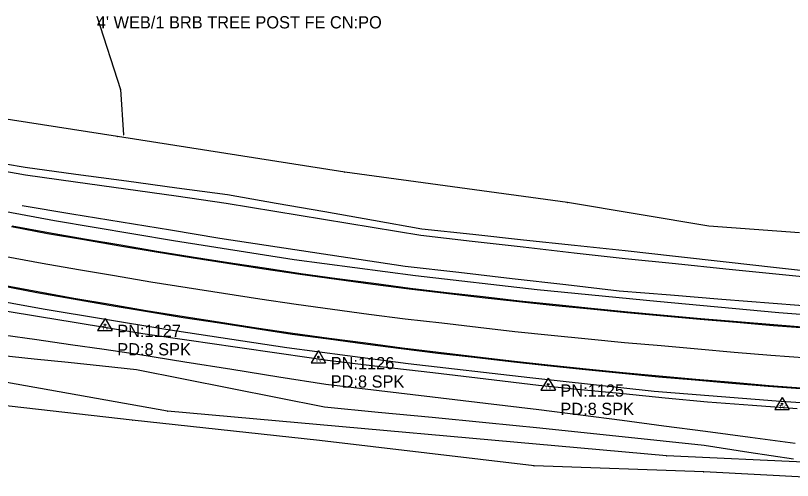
# Model space of a CAD drawing. Extents: x 878399 to 889864, y 1564003 to 1567413.
# Drawn here: x 886472.5 to 886790, y 1564428.6 to 1564618.5 of the extents above; entities that cross this region are included whole.
import ezdxf

# ---------------------------------------------------------------- set-up
doc = ezdxf.new("R2010")
doc.units = 0
for name, color, linetype in [('S_DITCHLINE', 7, 'Continuous'), ('S_EDGE_PAVEMENT', 7, 'Continuous'), ('S_FENCE', 7, 'Continuous'), ('S_FENCE_ANNOT', 7, 'Continuous'), ('S_FIBER_OPTIC_CABLE', 7, 'Continuous'), ('S_MSC_PT_SYM', 7, 'Continuous'), ('S_PAVEMENT_CROWN', 7, 'Continuous'), ('S_SECONDARY_CTL', 7, 'Continuous'), ('S_SECONDARY_CTL_ANNOT', 7, 'Continuous'), ('S_SHOULDER', 7, 'Continuous'), ('S_UTL_PT_SYM', 7, 'Continuous')]:
    doc.layers.add(name, color=color, linetype=linetype)

msp = doc.modelspace()

# ---------------------------------------------------------------- linework, layer by layer
at = {"layer": 'S_DITCHLINE'}
for points in [[(886921.18, 1564509.16), (886900.59, 1564510.35), (886880, 1564511.54), (886859.42, 1564512.73), (886838.83, 1564513.91), (886821.46, 1564513.53), (886804.1, 1564513.14), (886783.47, 1564515.43), (886762.84, 1564517.72), (886742.22, 1564520.01), (886721.59, 1564522.3), (886700.83, 1564524.54), (886680.07, 1564526.78), (886659.31, 1564529.03), (886638.55, 1564531.27), (886618.68, 1564534.76), (886598.81, 1564538.24), (886578.94, 1564541.73), (886559.07, 1564545.22), (886538.41, 1564548), (886517.75, 1564550.79), (886497.08, 1564553.58), (886476.42, 1564556.37), (886460.17, 1564559.13)], [(886803.75, 1564510.75), (886783.22, 1564512.83), (886762.69, 1564514.91), (886742.15, 1564516.99), (886721.62, 1564519.07), (886700.75, 1564521.45), (886679.88, 1564523.82), (886659.01, 1564526.2), (886638.14, 1564528.58), (886618.25, 1564531.87), (886598.36, 1564535.16), (886578.47, 1564538.45), (886558.58, 1564541.75), (886538.06, 1564544.63), (886517.54, 1564547.5), (886497.01, 1564550.38), (886476.49, 1564553.26), (886460.26, 1564556.16)], [(886791.03, 1564443.59), (886772.71, 1564446.08), (886754.4, 1564448.57), (886737.37, 1564450.78), (886720.35, 1564453), (886703.32, 1564455.21), (886686.3, 1564457.42), (886664.55, 1564460), (886642.79, 1564462.57), (886621.04, 1564465.15), (886599.29, 1564467.72), (886580.08, 1564470.79), (886560.87, 1564473.86), (886541.67, 1564476.93), (886522.46, 1564480.01), (886508.69, 1564482), (886494.93, 1564483.99), (886481.16, 1564485.98), (886467.4, 1564487.97)], [(886790.33, 1564437.19), (886772.14, 1564439.98), (886753.94, 1564442.77), (886737.12, 1564444.57), (886720.3, 1564446.37), (886703.47, 1564448.17), (886686.65, 1564449.97), (886664.66, 1564452.1), (886642.67, 1564454.24), (886620.68, 1564456.38), (886598.69, 1564458.52), (886579.49, 1564462.35), (886560.28, 1564466.17), (886541.08, 1564469.99), (886521.88, 1564473.81), (886507.94, 1564475.25), (886493.99, 1564476.69), (886480.05, 1564478.13), (886466.11, 1564479.57)]]:
    msp.add_lwpolyline(points, dxfattribs=at)
at = {"layer": 'S_EDGE_PAVEMENT'}
for points in [[(886470.81, 1564532.26), (886485.56, 1564529.5), (886485.56, 1564529.5), (886500.34, 1564526.95), (886515.13, 1564524.44), (886529.92, 1564521.93), (886544.28, 1564519.61), (886559.1, 1564517.32), (886573.93, 1564515.02), (886588.77, 1564512.79), (886603.63, 1564510.79), (886618.5, 1564508.79), (886633.37, 1564506.8), (886648.27, 1564505.06), (886663.18, 1564503.35), (886678.08, 1564501.65), (886693.01, 1564500.07), (886707.39, 1564498.64), (886722.32, 1564497.17), (886737.26, 1564495.74), (886752.2, 1564494.45), (886752.2, 1564494.45), (886767.15, 1564493.17), (886782.1, 1564491.89), (886797.05, 1564490.73)], [(886471.14, 1564532.59), (886485.89, 1564529.83), (886485.89, 1564529.83), (886500.67, 1564527.29), (886515.46, 1564524.77), (886530.25, 1564522.26), (886544.6, 1564519.94), (886559.43, 1564517.65), (886574.25, 1564515.35), (886589.09, 1564513.12), (886603.96, 1564511.12), (886618.82, 1564509.13), (886633.69, 1564507.13), (886648.59, 1564505.39), (886663.5, 1564503.68), (886678.4, 1564501.98), (886693.33, 1564500.4), (886707.71, 1564498.98), (886722.64, 1564497.5), (886737.57, 1564496.07), (886752.52, 1564494.78), (886752.52, 1564494.78), (886767.46, 1564493.5), (886782.41, 1564492.22), (886797.37, 1564491.06)], [(886466.46, 1564508.17), (886481.19, 1564505.34), (886481.19, 1564505.34), (886481.19, 1564505.34), (886495.97, 1564502.74), (886495.97, 1564502.74), (886510.75, 1564500.21), (886525.54, 1564497.69), (886525.54, 1564497.69), (886541, 1564495.16), (886541, 1564495.16), (886555.83, 1564492.89), (886570.66, 1564490.62), (886570.66, 1564490.62), (886585.49, 1564488.37), (886585.49, 1564488.37), (886600.36, 1564486.39), (886600.36, 1564486.39), (886600.36, 1564486.39), (886615.23, 1564484.41), (886615.23, 1564484.41), (886630.1, 1564482.43), (886630.1, 1564482.43), (886645, 1564480.61), (886645, 1564480.61), (886645, 1564480.61), (886659.9, 1564478.86), (886659.9, 1564478.86), (886659.9, 1564478.86), (886674.8, 1564477.1), (886674.8, 1564477.1), (886674.8, 1564477.1), (886689.71, 1564475.46), (886705.38, 1564473.88), (886720.31, 1564472.38), (886720.31, 1564472.38), (886735.24, 1564470.9), (886735.24, 1564470.9), (886735.24, 1564470.9), (886750.19, 1564469.62), (886750.19, 1564469.62), (886765.13, 1564468.34), (886765.13, 1564468.34), (886765.13, 1564468.34), (886780.08, 1564467.06), (886795.04, 1564465.92)], [(886466.79, 1564508.51), (886481.52, 1564505.68), (886481.52, 1564505.68), (886481.52, 1564505.68), (886496.29, 1564503.07), (886496.29, 1564503.07), (886511.08, 1564500.55), (886525.87, 1564498.02), (886525.87, 1564498.02), (886541.32, 1564495.49), (886541.32, 1564495.49), (886556.15, 1564493.22), (886570.98, 1564490.95), (886570.98, 1564490.95), (886585.82, 1564488.71), (886585.82, 1564488.71), (886600.69, 1564486.72), (886600.69, 1564486.72), (886600.69, 1564486.72), (886615.56, 1564484.74), (886615.56, 1564484.74), (886630.42, 1564482.76), (886630.42, 1564482.76), (886645.32, 1564480.95), (886645.32, 1564480.95), (886645.32, 1564480.95), (886660.21, 1564479.19), (886660.21, 1564479.19), (886660.21, 1564479.19), (886675.11, 1564477.44), (886675.11, 1564477.44), (886675.11, 1564477.44), (886690.03, 1564475.79), (886705.7, 1564474.21), (886720.63, 1564472.71), (886720.63, 1564472.71), (886735.55, 1564471.23), (886735.55, 1564471.23), (886735.55, 1564471.23), (886750.5, 1564469.95), (886750.5, 1564469.95), (886765.45, 1564468.67), (886765.45, 1564468.67), (886765.45, 1564468.67), (886780.39, 1564467.39), (886795.35, 1564466.26)]]:
    msp.add_lwpolyline(points, dxfattribs=at)
at = {"layer": 'S_FENCE'}
for p, q in [((886505.67, 1564618.21), (886515.41, 1564588.28)), ((886515.41, 1564588.28), (886516.64, 1564569.76)), ((886514.17, 1564569.01), (886437.4, 1564581)), ((886607, 1564554.55), (886514.17, 1564569.01)), ((886698.08, 1564542.05), (886607, 1564554.55)), ((886755.78, 1564532.44), (886698.08, 1564542.05)), ((886792.8, 1564529.65), (886755.78, 1564532.44)), ((886520.18, 1564453.2), (886463.29, 1564459.69)), ((886596.68, 1564444.91), (886520.18, 1564453.2)), ((886684.35, 1564434.5), (886596.68, 1564444.91)), ((886753.69, 1564432.05), (886684.35, 1564434.5)), ((886802.43, 1564429.46), (886753.69, 1564432.05))]:
    msp.add_line(p, q, dxfattribs=at)
at = {"layer": 'S_FIBER_OPTIC_CABLE'}
for p, q in [((886534.49, 1564456.86), (886416.68, 1564477.84)), ((886738.45, 1564438.6), (886534.49, 1564456.86)), ((886826.97, 1564434.45), (886738.45, 1564438.6))]:
    msp.add_line(p, q, dxfattribs=at)
at = {"layer": 'S_MSC_PT_SYM'}
for points in [[(886505.67, 1564618.21), (886505.67, 1564618.26), (886505.67, 1564618.21), (886505.62, 1564618.21), (886505.67, 1564618.21), (886505.67, 1564618.16), (886505.67, 1564618.21), (886505.72, 1564618.21)], [(886515.41, 1564588.28), (886515.41, 1564588.33), (886515.41, 1564588.28), (886515.36, 1564588.28), (886515.41, 1564588.28), (886515.41, 1564588.23), (886515.41, 1564588.28), (886515.46, 1564588.28)], [(886516.64, 1564569.76), (886516.64, 1564569.81), (886516.64, 1564569.76), (886516.59, 1564569.76), (886516.64, 1564569.76), (886516.64, 1564569.71), (886516.64, 1564569.76), (886516.69, 1564569.76)], [(886514.17, 1564569.01), (886514.17, 1564569.06), (886514.17, 1564569.01), (886514.12, 1564569.01), (886514.17, 1564569.01), (886514.17, 1564568.96), (886514.17, 1564569.01), (886514.22, 1564569.01)], [(886607, 1564554.55), (886607, 1564554.6), (886607, 1564554.55), (886606.95, 1564554.55), (886607, 1564554.55), (886607, 1564554.5), (886607, 1564554.55), (886607.05, 1564554.55)], [(886698.08, 1564542.05), (886698.08, 1564542.1), (886698.08, 1564542.05), (886698.03, 1564542.05), (886698.08, 1564542.05), (886698.08, 1564542), (886698.08, 1564542.05), (886698.13, 1564542.05)], [(886755.78, 1564532.44), (886755.78, 1564532.49), (886755.78, 1564532.44), (886755.73, 1564532.44), (886755.78, 1564532.44), (886755.78, 1564532.39), (886755.78, 1564532.44), (886755.83, 1564532.44)], [(886520.18, 1564453.2), (886520.18, 1564453.25), (886520.18, 1564453.2), (886520.13, 1564453.2), (886520.18, 1564453.2), (886520.18, 1564453.15), (886520.18, 1564453.2), (886520.23, 1564453.2)], [(886596.68, 1564444.91), (886596.68, 1564444.96), (886596.68, 1564444.91), (886596.63, 1564444.91), (886596.68, 1564444.91), (886596.68, 1564444.86), (886596.68, 1564444.91), (886596.73, 1564444.91)], [(886684.35, 1564434.5), (886684.35, 1564434.55), (886684.35, 1564434.5), (886684.3, 1564434.5), (886684.35, 1564434.5), (886684.35, 1564434.45), (886684.35, 1564434.5), (886684.4, 1564434.5)], [(886753.69, 1564432.05), (886753.69, 1564432.1), (886753.69, 1564432.05), (886753.64, 1564432.05), (886753.69, 1564432.05), (886753.69, 1564432), (886753.69, 1564432.05), (886753.74, 1564432.05)]]:
    msp.add_lwpolyline(points, dxfattribs=at)
at = {"layer": 'S_PAVEMENT_CROWN'}
msp.add_lwpolyline([(886468.6, 1564520.01), (886483.36, 1564517.33), (886498.14, 1564514.77), (886512.92, 1564512.22), (886527.72, 1564509.71), (886542.63, 1564507.36), (886557.46, 1564505.03), (886572.28, 1564502.69), (886572.28, 1564502.69), (886587.14, 1564500.62), (886602, 1564498.56), (886616.86, 1564496.51), (886631.74, 1564494.64), (886646.64, 1564492.89), (886661.54, 1564491.15), (886676.45, 1564489.46), (886691.39, 1564487.97), (886706.4, 1564486.46), (886721.33, 1564484.96), (886721.33, 1564484.96), (886721.33, 1564484.96), (886736.27, 1564483.62), (886736.27, 1564483.62), (886751.22, 1564482.29), (886766.16, 1564480.97), (886781.11, 1564479.75), (886781.11, 1564479.75), (886781.11, 1564479.75), (886796.07, 1564478.62)], dxfattribs=at)
at = {"layer": 'S_SECONDARY_CTL'}
for p, q in [((886509.02, 1564494.75), (886506.01, 1564489.8)), ((886509.02, 1564494.75), (886511.97, 1564489.8)), ((886506.01, 1564489.8), (886511.97, 1564489.8)), ((886596.24, 1564481.59), (886593.23, 1564476.64)), ((886596.24, 1564481.59), (886599.18, 1564476.64)), ((886593.23, 1564476.64), (886599.18, 1564476.64)), ((886690.12, 1564470.4), (886687.11, 1564465.45)), ((886690.12, 1564470.4), (886693.07, 1564465.45)), ((886687.11, 1564465.45), (886693.07, 1564465.45)), ((886785.71, 1564462.45), (886782.7, 1564457.5)), ((886785.71, 1564462.45), (886788.65, 1564457.5)), ((886782.7, 1564457.5), (886788.65, 1564457.5))]:
    msp.add_line(p, q, dxfattribs=at)
for centre, radius in [((886509.02, 1564492.14), 0.311), ((886509.02, 1564492.14), 0.183), ((886509.02, 1564492.14), 0.103), ((886596.24, 1564478.98), 0.311), ((886596.24, 1564478.98), 0.183), ((886596.24, 1564478.98), 0.103), ((886690.12, 1564467.79), 0.311), ((886690.12, 1564467.79), 0.183), ((886690.12, 1564467.79), 0.103), ((886785.71, 1564459.84), 0.311), ((886785.71, 1564459.84), 0.183), ((886785.71, 1564459.84), 0.103)]:
    msp.add_circle(centre, radius, dxfattribs=at)
at = {"layer": 'S_SHOULDER'}
for points in [[(886439.19, 1564543.9), (886488.35, 1564534.77), (886536.94, 1564526.51), (886586.36, 1564518.81), (886635.93, 1564512.26), (886685.62, 1564506.57), (886734.54, 1564501.74), (886784.34, 1564497.16), (886834.2, 1564493.36), (886883.7, 1564489.95), (886933.63, 1564487.46), (886983.53, 1564484.37), (887033.43, 1564481.47), (887083.36, 1564478.88), (887132.96, 1564476.84), (887182.9, 1564474.75), (887232.84, 1564472.73), (887282.79, 1564471.29), (887332.75, 1564469.72), (887382.66, 1564467.88), (887432.62, 1564466.36), (887482.58, 1564464.72)], [(886922.11, 1564490.93), (886901.24, 1564492.13), (886880.38, 1564493.33), (886859.52, 1564494.53), (886838.66, 1564495.73), (886820.87, 1564497.44), (886803.09, 1564499.15), (886782.11, 1564500.84), (886761.13, 1564502.52), (886740.14, 1564504.2), (886719.16, 1564505.89), (886697.29, 1564508.41), (886675.42, 1564510.92), (886653.55, 1564513.44), (886631.69, 1564515.96), (886612.76, 1564518.84), (886593.84, 1564521.71), (886574.92, 1564524.59), (886556, 1564527.46), (886535.8, 1564530.77), (886515.61, 1564534.08), (886495.42, 1564537.38), (886475.22, 1564540.69)], [(886434.5, 1564507.62), (886483.69, 1564498.68), (886533.94, 1564490.3), (886583.39, 1564482.88), (886632.96, 1564476.31), (886682.65, 1564470.63), (886733.41, 1564465.04), (886783.26, 1564461.07), (886833.15, 1564457.67), (886883.53, 1564454.57), (886933.43, 1564451.65), (886983.34, 1564448.74), (887033.23, 1564445.65), (887083.15, 1564442.94), (887133.5, 1564440.74), (887183.43, 1564438.72), (887233.38, 1564436.89), (887283.33, 1564435.19), (887333.28, 1564433.45), (887383.27, 1564431.95), (887433.22, 1564430.22), (887483.18, 1564428.56)], [(886791.92, 1564457.77), (886773.6, 1564459.15), (886755.29, 1564460.53), (886738, 1564462.23), (886720.72, 1564463.93), (886703.43, 1564465.64), (886686.15, 1564467.34), (886664.6, 1564469.9), (886643.05, 1564472.46), (886621.5, 1564475.03), (886599.95, 1564477.59), (886581.1, 1564480.29), (886562.25, 1564483), (886543.39, 1564485.7), (886524.54, 1564488.4), (886510.45, 1564490.72), (886496.36, 1564493.05), (886482.28, 1564495.37), (886468.19, 1564497.69)]]:
    msp.add_lwpolyline(points, dxfattribs=at)
at = {"layer": 'S_UTL_PT_SYM'}
for points in [[(886534.49, 1564456.86), (886534.49, 1564456.91), (886534.49, 1564456.86), (886534.44, 1564456.86), (886534.49, 1564456.86), (886534.49, 1564456.81), (886534.49, 1564456.86), (886534.54, 1564456.86)], [(886738.45, 1564438.6), (886738.45, 1564438.65), (886738.45, 1564438.6), (886738.4, 1564438.6), (886738.45, 1564438.6), (886738.45, 1564438.55), (886738.45, 1564438.6), (886738.5, 1564438.6)]]:
    msp.add_lwpolyline(points, dxfattribs=at)

# ---------------------------------------------------------------- texts
at = {"layer": 'S_FENCE_ANNOT'}
msp.add_text("4' WEB/1 BRB TREE POST FE CN:PO", height=5, dxfattribs=at).set_placement((886505.67, 1564613.21))
at = {"layer": 'S_SECONDARY_CTL'}
for p in [(886507.81, 1564490.13), (886595.03, 1564476.97), (886688.92, 1564465.78), (886784.5, 1564457.83)]:
    msp.add_text('TV', height=1.5, rotation=360, dxfattribs=at).set_placement(p)
at = {"layer": 'S_SECONDARY_CTL_ANNOT'}
for s, p in [('PN:1127', (886514.02, 1564487.14)), ('PD:8 SPK', (886514.02, 1564479.64)), ('PN:1126', (886601.24, 1564473.98)), ('PD:8 SPK', (886601.24, 1564466.48)), ('PN:1125', (886695.12, 1564462.79)), ('PD:8 SPK', (886695.12, 1564455.29))]:
    msp.add_text(s, height=5, dxfattribs=at).set_placement(p)

doc.saveas('drawing.dxf')
